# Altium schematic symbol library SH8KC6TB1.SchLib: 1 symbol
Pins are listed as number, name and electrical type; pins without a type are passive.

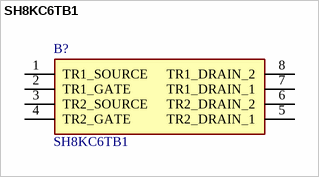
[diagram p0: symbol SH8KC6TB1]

## SH8KC6TB1
designator B?
60V Dual Nch+Nch, SOP8, Power MOSFET; Manufacturer_Name: ROHM Semiconductor; Geometry.Height: 1.75mm
footprint SOIC127P600X175-8N
pins: 1 TR1_SOURCE, 2 TR1_GATE, 3 TR2_SOURCE, 4 TR2_GATE, 5 TR2_DRAIN_1, 6 TR2_DRAIN_2, 7 TR1_DRAIN_1, 8 TR1_DRAIN_2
